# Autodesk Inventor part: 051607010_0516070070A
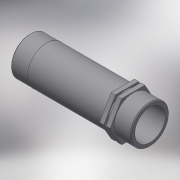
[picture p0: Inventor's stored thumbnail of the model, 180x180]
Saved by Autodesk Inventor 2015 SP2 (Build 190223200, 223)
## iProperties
Created: 2017-05
Part Number: 051607010_0516070070A
Material: Generic
Description: PLASSON RISER 1"-1"
Document SubType Name: Modeling
Designer: KIM
Mass: 20.3153 g
Surface Area: 184.457 cm^2
Volume: 20.3153 cm^3
Density: 1 g/cm^3
Appearance: Default
Author: KIM
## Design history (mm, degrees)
derived "051607.ipt"
feature "Solid1::051607.ipt"
tag "TaggingFeature1"
body "Solid1"
other parameters: "d1" = 33.249, "d2" = 36, "d3" = 26.5992, "d5" = 19, "d6" = 4.75, "d8" = 0.95, "d12" = 0, "d13" = 2.375, "d15" = 19, "d17" = 0, "d18" = 33.249, "R_" = 33.249, "E_" = 36, "l_2" = 19, "R_1" = 33.249
